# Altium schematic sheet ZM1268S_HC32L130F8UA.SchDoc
size A3; DocumentNumber: 3; PageSetup: Record=PageOptions|CenterHorizontal=True|CenterVertical=True|PrintScale=1.00|XCorrection=1.00|YCorrection=1.00|PrintKind=1|BorderSize=5000000|LeftOffset=0|BottomOffset=0|Orientation=2|PaperLength=1000|PaperWidth=1000|Scale=100|PaperSource=7|PrintQuality=600|MediaType=1|DitherType=10|PaperKind=A4|PrintScaleMode=1
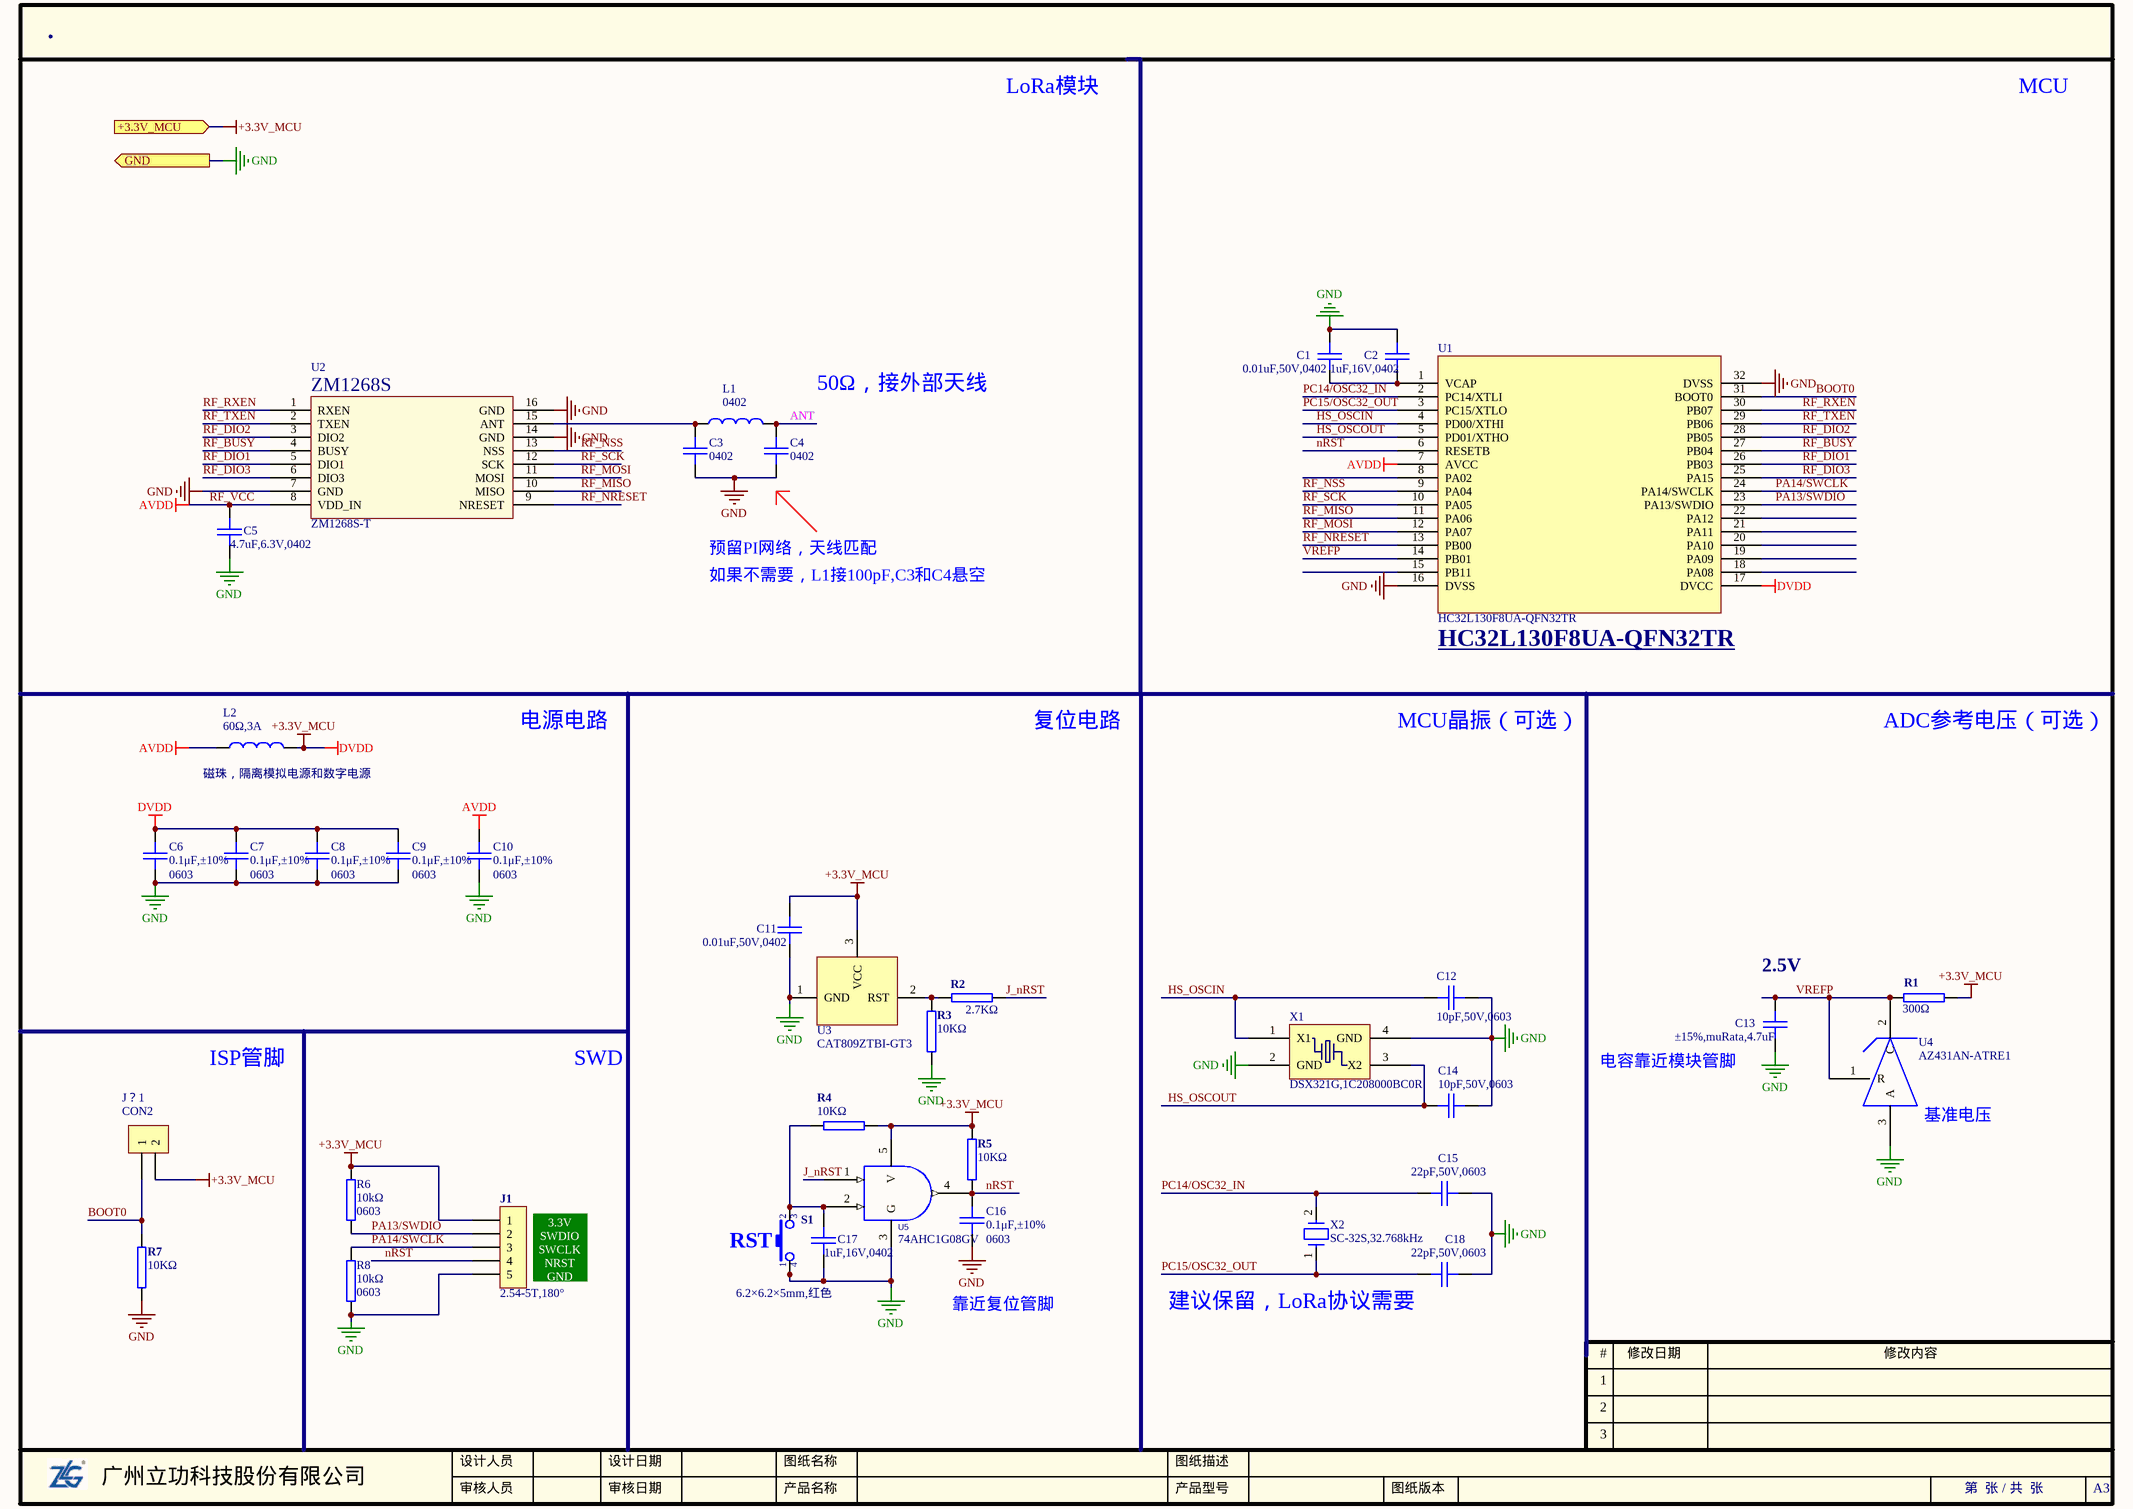
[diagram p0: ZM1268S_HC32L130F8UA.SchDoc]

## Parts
C1  0.01uF,50V,0402  [0402C]
C2  1uF,16V,0402  [0402C]
C3  封装: 0402  [0402C]  (hidden comment: 4.7uF,6.3V,0402)
C4  封装: 0402  [0402C]  (hidden comment: 4.7uF,6.3V,0402)
C5  4.7uF,6.3V,0402  [0402C]
C6  封装: 0603  [0201C]  (hidden comment: 0.1μF,±10%)
C7  封装: 0603  [0201C]  (hidden comment: 0.1μF,±10%)
C8  封装: 0603  [0201C]  (hidden comment: 0.1μF,±10%)
C9  封装: 0603  [0201C]  (hidden comment: 0.1μF,±10%)
C10  封装: 0603  [0201C]  (hidden comment: 0.1μF,±10%)
C11  0.01uF,50V,0402  [0402C]
C12  10pF,50V,0603  [0603C]
C13  ±15%,muRata,4.7uF  [0603C]
C14  10pF,50V,0603  [0603C]
C15  22pF,50V,0603  [0603C]
C16  封装: 0603  [0201C]  (hidden comment: 0.1μF,±10%)
C17  1uF,16V,0402  [0402C]
C18  22pF,50V,0603  [0603C]
J1  2.54-5T,180°  [CON250P580W100D50S-5DIP]
J？1  CON2  [SIP-2-2.54]
L1  封装: 0402  [0402L]  (hidden comment: LQG15HS56NJ02D,56nH)
L2  60Ω,3A  [0805L]
R1  300Ω  [0603R]
R2  2.7KΩ  [0603R]
R3  10KΩ  [0603R]
R4  10KΩ  [0603R]
R5  10KΩ  [0603R]
R6  封装: 0603  [0603R]  (hidden comment: 10kΩ)
R7  10KΩ  [0603R]
R8  封装: 0603  [0603R]  (hidden comment: 10kΩ)
S1  6.2×6.2×5mm,红色  [KEY-6S]
U1  HC32L130F8UA-QFN32TR  [QFP40P900X900X160-64N]
U2  ZM1268S-T  [ZM1268S-T_REVB]
U3  CAT809ZTBI-GT3  [SOT-23]
U4  AZ431AN-ATRE1  [SOT-23]
U5  value 74AHC1G08GV  [SOT-23-5]  (hidden comment: 74AHC1G08)
X1  DSX321G,1C208000BC0R  [OSCCC250X320X100-4N]  (no BOM)
X2  SC-32S,32.768kHz  [XTAL320X150X90]  (no BOM)

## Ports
+3.3V_MCU (in), GND (out)

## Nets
+3.3V_MCU: C6.1 C7.1 C8.1 C9.1 C11.1 J1.1 J？1.2 L2.2 R1.2 R4.2 R5.2 R6.2 U1.17(DVCC) U3.3(VCC) U5.5(V) ; port +3.3V_MCU  [also labelled DVDD]
GND: C1.1 C2.1 C3.2 C4.2 C5.2 C6.2 C7.2 C8.2 C9.2 C10.2 C11.2 C12.2 C13.2 C14.2 C15.2 C16.2 C17.2 C18.2 J1.5 R3.1 R7.2 R8.1 S1.1 S1.4 U1.16(DVSS) U1.32(DVSS) U2.7(GND) U2.14(GND) U2.16(GND) U3.1(GND) U4.3(A) U5.3(G) X1.2(GND) X1.4(GND) ; port GND
RF_VCC: C5.1 C10.1 L2.1 U1.7(AVCC) U2.8(VDD_IN)  [also labelled AVDD]
ANT: C4.1 L1.2
BOOT0: J？1.1 R7.1 U1.31(BOOT0)
HS_OSCIN: C12.1 U1.4(PD00/XTHI) X1.1(X1)
HS_OSCOUT: C14.1 U1.5(PD01/XTHO) X1.3(X2)
J_nRST: R2.2 U5.1(IN_B)
nRST: C16.1 J1.4 R5.1 U1.6(RESETB) U5.4(OUT_Y)
PA13/SWDIO: J1.2 R6.1 U1.23(PA13/SWDIO)
PA14/SWCLK: J1.3 R8.2 U1.24(PA14/SWCLK)
PC14/OSC32_IN: C15.1 U1.2(PC14/XTLI) X2.2
PC15/OSC32_OUT: C18.1 U1.3(PC15/XTLO) X2.1
RF_BUSY: U1.27(PB04) U2.4(BUSY)
RF_DIO1: U1.26(PB03) U2.5(DIO1)
RF_DIO2: U1.28(PB05) U2.3(DIO2)
RF_DIO3: U1.25(PA15) U2.6(DIO3)
RF_MISO: U1.11(PA06) U2.10(MISO)
RF_MOSI: U1.12(PA07) U2.11(MOSI)
RF_NRESET: U1.13(PB00) U2.9(NRESET)
RF_NSS: U1.9(PA04) U2.13(NSS)
RF_RXEN: U1.30(PB07) U2.1(RXEN)
RF_SCK: U1.10(PA05) U2.12(SCK)
RF_TXEN: U1.29(PB06) U2.2(TXEN)
VREFP: C13.1 R1.1 U1.14(PB01) U4.1(R) U4.2(C)
NetC1_2: C1.2 C2.2 U1.1(VCAP)
NetC3_1: C3.1 L1.1 U2.15(ANT)
NetC17_1: C17.1 R4.1 S1.2 S1.3 U5.2(IN_A)
NetR2_1: R2.1 R3.2 U3.2(RST)

Not connected (* = marked no-connect by the designer): U1 8(PA02) 15(PB11) 18(PA08) 19(PA09) 20(PA10) 21(PA11) 22(PA12)

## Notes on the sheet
- LoRa模块
- MCU
- 50Ω，接外部天线
- 预留PI网络，天线匹配
- 如果不需要，L1接100pF,C3和C4悬空
- (near U1) HC32L130F8UA-QFN32TR
- (near L2) 磁珠，隔离模拟电源和数字电源
- 电源电路
- 复位电路
- MCU晶振（可选）
- ADC参考电压（可选）
- (near C13) 2.5V
- ISP管脚
- SWD
- 电容靠近模块管脚
- (near U4) 基准电压
- (near J1) 3.3V
  SWDIO
  SWCLK
  NRST
  GND
- 靠近复位管脚
- (near X2) 建议保留，LoRa协议需要
- Labels drawn without touching a wire or pin: RST

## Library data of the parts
C1 C11 = 02.01.00275: GRM155R71H103KA88D,0402,MURATA,0.01uF,X7R,±10%,50V,; 旧物料代码: 1.02.17.0019; 名称: 电容; 封装: 0402; 贴片和直插: SMT; 器件优选方案: 通用物料
C2 C17 = 02.01.00333: GRM155R61C105KA12D,0402,MURATA,1uF,X5R,±10%,16V,; 旧物料代码: 1.02.17.0092; 名称: 电容; 封装: 0402; 贴片和直插: SMT; PCB备注: 无数据手册，依据采购部提供的信息添加的封装。; 器件优选方案: 通用物料
C3 C4 = 02.01.00315: GRM155R60J475ME87D,0402,MURATA,4.7uF,X5R,±20%,6.3V,; 旧物料代码: 1.02.17.0073; 名称: 电容; 贴片和直插: SMT; 器件优选方案: 推荐使用
C5 = 02.01.00315: GRM155R60J475ME87D,0402,MURATA,4.7uF,X5R,±20%,6.3V,; 旧物料代码: 1.02.17.0073; 名称: 电容; 封装: 0402; 贴片和直插: SMT; 器件优选方案: 推荐使用
C6-C10 C16 = 02.01.00416: GRM033R61A104KE15D,0201,muRata,0.1μF,X5R ±10%,10V; 名称: 陶瓷电容; 贴片和直插: SMT; 器件优选方案: 通用物料
C12 C14 = 02.01.00129: 10P,0603,MURATA,10pF,COG,±5%,50V,; 旧物料代码: 1.02.01.0031; 名称: 电容; 封装: 0603; 贴片和直插: SMT; 器件优选方案: 不推荐使用
C13 = 02.01.00449: GRM188R61C475KAAJD,4.7uF,16V,±15%,X5R,0603,muRata; 名称: 电容; 封装: 0603; 贴片和直插: SMT; PCB备注: 190510CZY; 器件优选方案: 通用物料
C15 C18 = 02.01.00009: GRM1885C1H220JA01D,0603,MURATA,22pF,COG,±5%,50V,; 旧物料代码: 1.02.01.0005; 名称: 电容; 封装: 0603; 贴片和直插: SMT; 器件优选方案: 不推荐使用
J1 = 1.10.06.0012: 2.54-5T,180°,,*; 名称: 插座; 贴片和直插: THT; PCB备注: xhm-lq-wyy-150123 / 150918mxz; 器件优选方案: 正常状态，可以选用
J？1 = CON2: Connector
L1 = 03.01.00539: LQG15HS56NJ02D,56nH,250mA,±5%,0402,muRata; 名称: 电感; 贴片和直插: SMT; PCB备注: 190510CZY; 器件优选方案: 待导入物料
L2 = 1.03.03.0015: 60Ω,3A,DCR30mΩ,BH05Y354S-60R,SMD,0805,丰晶,RoHS; 名称: 磁珠; 封装: 0805; 贴片和直插: SMT; 器件优选方案: 正常状态，可以选用
R1 = 1.01.01.0030: 300Ω,0603,*,RoHS; 名称: 电阻; 封装: 0603; 设备封装名称: R0603_300R; 厂商: Ralec; 贴片和直插: SMT; 器件优选方案: 正常状态，可以选用
R2 = 1.01.01.0040: 2.7KΩ,0603,*,RoHS; 名称: 电阻; 封装: 0603; 设备封装名称: R0603_2.7K; 厂商: Ralec; 贴片和直插: SMT; 器件优选方案: 正常状态，可以选用
R3-R5 R7 = 1.01.01.0051: 10KΩ,0603,*,RoHS; 名称: 电阻; 封装: 0603; 设备封装名称: R0603_10K; 厂商: Ralec; 贴片和直插: SMT; 器件优选方案: 正常状态，可以选用
R6 R8 = 1.01.01.0052: 10KΩ,±1%,0603,*,RoHS; 名称: 电阻; 设备封装名称: R0603_10K_1%; 厂商: Ralec; 贴片和直插: SMT
S1 = 1.09.01.0004: 6.2×6.2×5mm,红色,DTSM-62R-V-T/R,SMD; 名称: 轻触按键; 贴片和直插: SMT; 器件优选方案: 正常状态，可以选用
U1 = HC32L130F8UA-QFN32TR: HC32L130F8UA-QFN32TR,华大半导体; 物料代码: 08.01.04536; 名称: 集成电路; 封装: LQFP-64; 贴片和直插: SMT; PCB备注: 200515CZY; 器件优选方案: 待导入物料
U2 = 78.04.00105: ZM1268S-T S0.04; 名称: LoRa模块; 厂商: ZHIYUAN; 贴片和直插: SMT; PCB备注: 200515CZY
U3 = 1.05.10.0708: CAT809ZTBI-GT3,SOT-23,ON,RoHS; 名称: 集成电路; 贴片和直插: SMT; PCB备注: 171109 YYF; 器件优选方案: 正常状态，可以选用
U4 = 1.05.09.0239: AZ431AN-ATRE1,Diodes,SOT-23,RoHS; 名称: 集成电路; 贴片和直插: SMT; PCB备注: 170516 hcj; 器件优选方案: 正常状态，可以选用
U5 = 1.05.05.0093: 74AHC1G08GV,SOT-753,NXP,RoHS; Manufacturer: PHILIPS; ID: 77; 名称: IC; 设备封装名称: SOT-753_74AHC1G08GV; 贴片和直插: SMT
X1 = 12.02.00214: DSX321G,1C208000BC0R,8.000MHZ,10ppm,12pF,SMT,KDS; 名称: 无源晶体振荡器; PCB备注: 190612 yyf; 器件优选方案: 待导入物料
X2 = 1.07.02.0056: SC-32S,32.768kHz,12.5pF,±20ppm,SMD3215,SII,RoHS; 名称: 晶振; 贴片和直插: SMT; PCB备注: 171129ZW; 器件优选方案: 正常状态，可以选用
